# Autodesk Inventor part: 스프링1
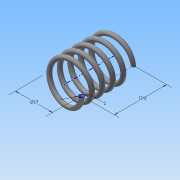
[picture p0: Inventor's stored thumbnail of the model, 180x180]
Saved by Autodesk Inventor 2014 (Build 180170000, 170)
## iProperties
Created: 2016-01
Part Number: 스프링1
Material: 강철, 탄소
Document SubType Name: Modeling
Designer: Administrator
Density: 1 g/cm^3
Appearance: 반연마
Mass: 0.821689 g
Surface Area: 16.7182 cm^2
Volume: 0.821689 cm^3
Author: Administrator
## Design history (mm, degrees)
sketch "스케치1"
  geometry: L1 (0, 0)-(8.5, 0); L2 (8.5, 0)-(8.5, 20.5); L3 (8.5, 20.5)-(0, 20.5); L4 (0, 20.5)-(0, 0); C1 r 1 at (8.5, 0)
  constraints: 8 end point, 2 parallel, 1 centre point, 1 coincident, 1 horizontal, 1 perpendicular
  dimensions: "d0" = 17 diameter of L2 L4; "d1" = 20.5 distance of L1.end L2.end (derived); "d2" = 2 diameter of C1
feature "코일1" pitch "d3" = 10; turns "d5" = 5; dims "d4" = 20.5 (= d1), "d6" = 0, angle "d7" = 90 deg, angle "d8" = 90 deg, "d9" = 0, "d10" = 0
node "작업 평면1"
sketch "스케치2"
  geometry: L1 (-9.5, 0)-(-7.5, 0) reference; 1 further point
  constraints: 1 horizontal alignment
extrude "돌출1" cut sketch "스케치2" distance "d12" = 10; taper "d13" = 0 deg
node "작업 평면2"
sketch "스케치3"
  geometry: L1 (-7.5, 0)-(-9.5, 0) reference; 1 further point
  constraints: 1 horizontal alignment
extrude "돌출2" cut sketch "스케치3" distance "d15" = 10; taper "d16" = 0 deg
node "솔리드1"
node "절단 모서리 투영1"
node "절단 모서리 투영2"
other parameters: "d11" = 0, "d14" = 20.5 (= d1)
